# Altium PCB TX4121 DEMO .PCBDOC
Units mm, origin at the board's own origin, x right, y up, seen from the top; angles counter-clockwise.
Board outline 43.09 x 22 mm, 3 copper layers (TopLayer, MidLayer5, BottomLayer); 14 components, 16 nets, 40 pads, 90 vias.
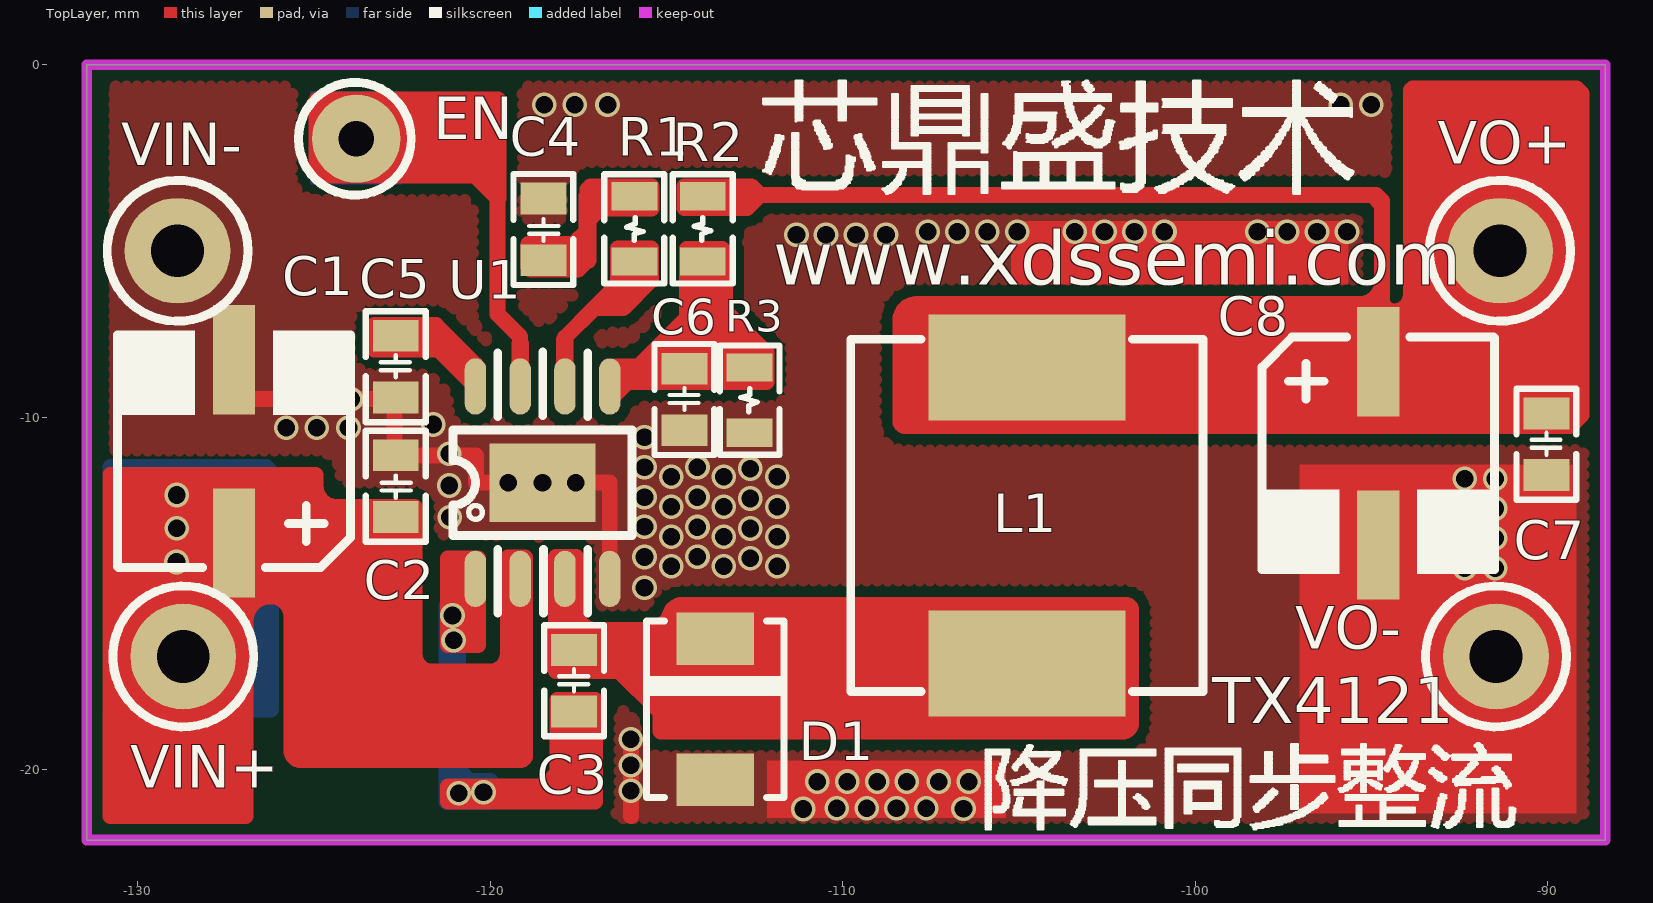
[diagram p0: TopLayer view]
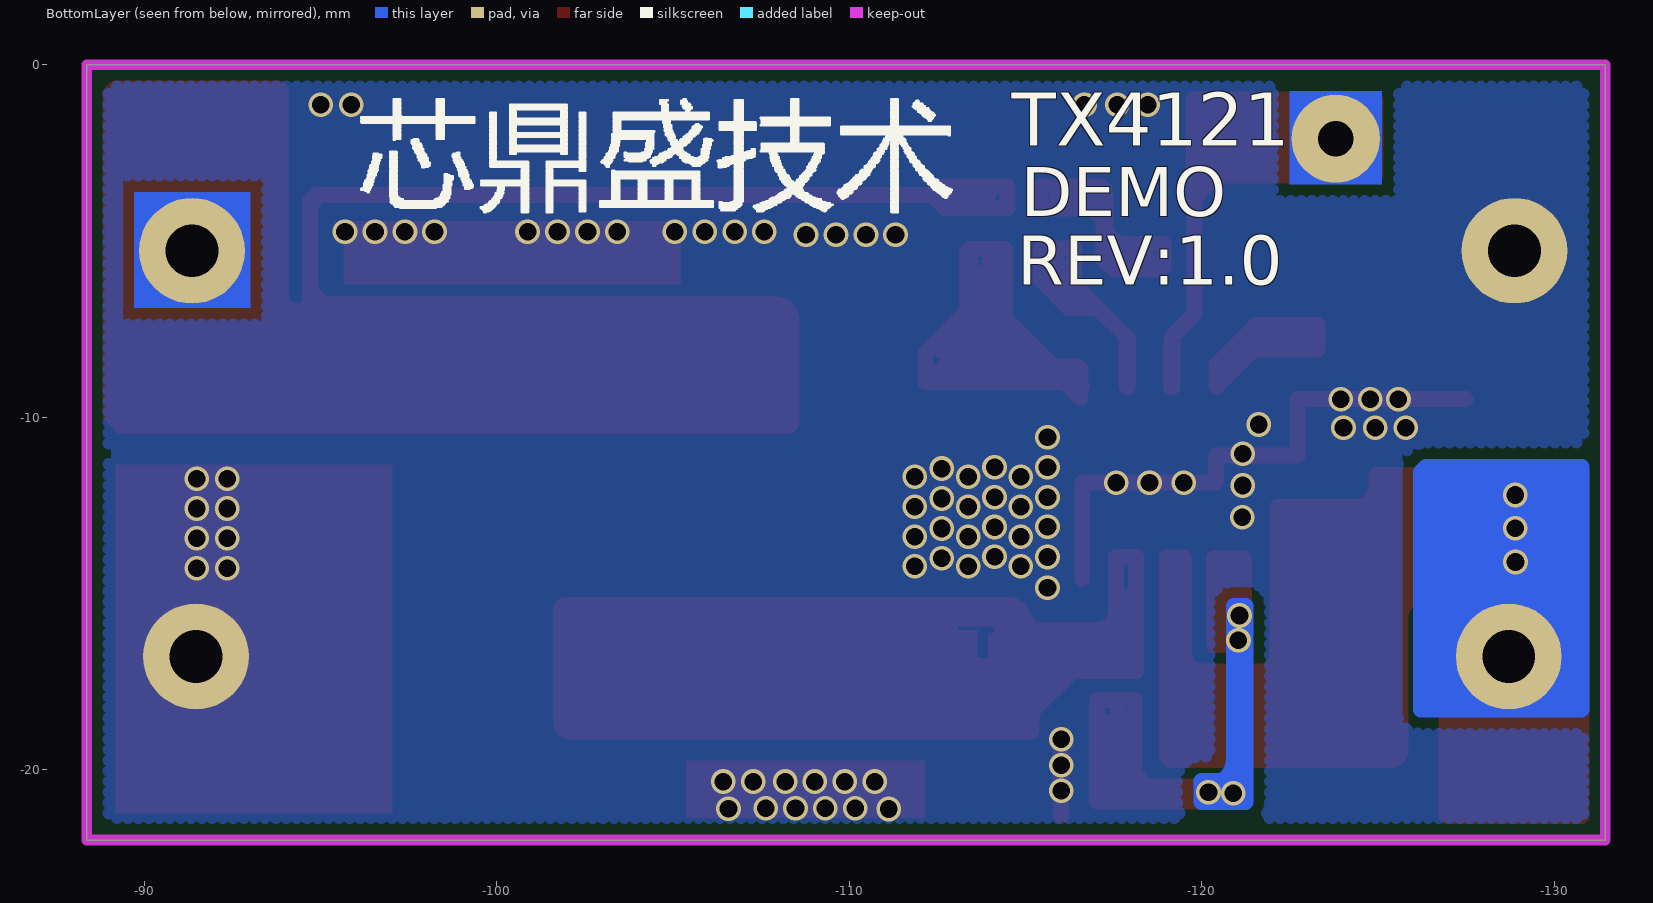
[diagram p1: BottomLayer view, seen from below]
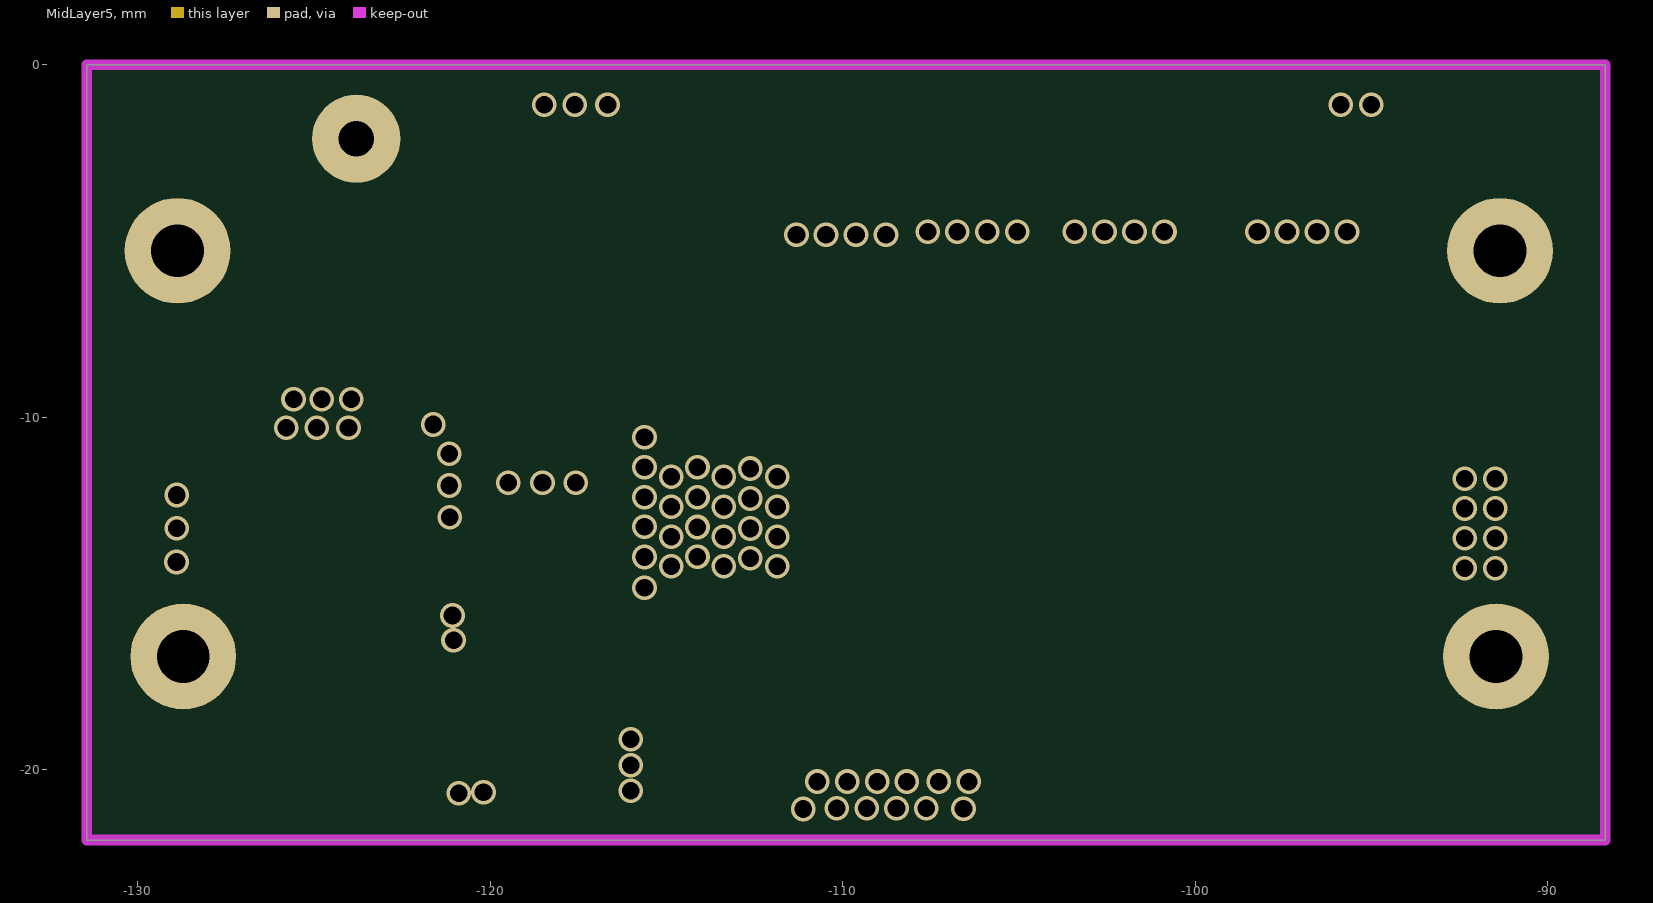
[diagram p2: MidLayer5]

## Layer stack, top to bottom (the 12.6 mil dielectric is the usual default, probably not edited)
TopLayer: signal copper 0.0356
Dielectric: dielectric 0.32, FR-4, Dk 4.8
MidLayer5: signal copper 0.0356
Dielectric: dielectric 0.32, FR-4, Dk 4.8
BottomLayer: signal copper 0.0356

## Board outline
-131.45,-22 -88.36,-22 -88.36,0 -131.45,0

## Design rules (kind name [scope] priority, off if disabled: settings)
Clearance [All] p1: gap=0.3
PlaneConnect [All] p1: planeconnectstyle=Direct reliefexpansion=0.508 reliefentries=4 reliefconductorwidth=0.254 reliefairgap=0.254
PolygonConnect [All] p1: connectstyle=Direct reliefconductorwidth=0.254 reliefentries=4 polygonreliefangle="90 Angle"
RoutingLayers [All] p1: top layer_v5=TRUE mid layer 5_v5=FALSE bottom layer_v5=TRUE
RoutingVias [All] p1: holewidth=0.711 width=1.27 viastyle="Through Hole" minholewidth=0.711 minwidth=1.27 maxholewidth=0.711 maxwidth=1.27
SilkscreenOverComponentPads [All] p1: minsilkscreentomaskgap=0.254
SolderMaskExpansion [All] p1: expansion=0.102
TestPointUsage [All] p1: valid=0 allowmultiple=FALSE
Testpoint [All] p1: side=15 testpointundercomponent=TRUE minsize=1.016 maxsize=2.54 preferedsize=1.524 minholesize=0.508 maxholesize=1.016 preferedholesize=0.813 testpointgrid=0.025 style=1023 order=0123456789
Width [All] p1: maxlimit=1 minlimit=0.3 preferedwidth=0.45
21 further rules are at their usual default settings.

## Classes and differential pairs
component class HX1304B: C1 C3 C4 C6 F1 L1 R1 R2 R3 U1

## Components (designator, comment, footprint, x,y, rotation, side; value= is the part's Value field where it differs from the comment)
C1 "100uF" C6.3*2.5W -127.27,-13.57 r180 top
C2 "100nF" C0805 -122.68,-11.96 r90 top
C3 "100nF" C0805 -117.62,-17.48 r270 top
C4 "100pF" C0805 -118.49,-4.675 r90 top
C5 "100nF" C0805 -122.68,-8.57 r270 top
C6 "47pF" C0805 -114.49,-9.5 r270 top
C7 "100nF" C0805 -90.03,-10.77 r270 top
C8 "100uF" C6.3*2.5W -94.8,-8.43 r0 top
D1 "" SMB -113.61,-18.29 r270 top
L1 "22uH" ls10*10 -104.77,-16.99 r270 top
R1 "300KΩ" R0805 -115.91,-4.66 r90 top
R2 "47kΩ" R0805 -113.97,-4.66 r270 top
R3 "10kΩ" R0805 -112.64,-9.52 r270 top
U1 "TX4121" ESOP8 -120.42,-14.59 r0 top

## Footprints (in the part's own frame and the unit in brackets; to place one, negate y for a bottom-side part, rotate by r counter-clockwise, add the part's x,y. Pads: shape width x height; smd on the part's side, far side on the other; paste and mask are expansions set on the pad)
C6.3*2.5W [mm]
  rect 1.2x3.1 smd: 1(0,0) 2(0,-5.2)
  silkscreen extent -3.3,-6.03 3.3,0.7
C0805 [mm]
  rect 0.9x1.3 smd: 1(-0.875,0) 2(0.875,0)
  silkscreen extent -1.58,-0.85 1.58,0.85
ESOP8 [mm]
  oval 0.61x1.6 smd: 1(0,0) 2(1.27,0) 3(2.54,0) 4(3.81,0) 5(3.81,5.46) 6(2.54,5.46) 7(1.27,5.46) 8(0,5.46)
  rect 3x2.23 smd: 9(1.905,2.73)
  silkscreen extent -0.64,-0.96 4.45,6.44
ls10*10 [mm]
  rect 3x5.6 smd: 1(0,0) 2(-8.4,0)
  silkscreen extent -9.2,-5 0.8,5
R0805 [mm]
  rect 0.8x1.3 smd: 1(-0.925,0) 2(0.925,0)
  silkscreen extent -1.55,-0.85 1.55,0.85
SMB [mm]
  rect 1.5x2.2 smd: 1(2,0) 2(-2,0)
  silkscreen extent -2.5,-1.97 2.5,1.95

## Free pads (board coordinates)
  round 2.5 hole 1: 0(-123.8,-2.1)
  round 3 hole 1.5: 2(-128.87,-5.28) 2(-128.71,-16.79) 2(-91.46,-16.79) 2(-91.35,-5.28)

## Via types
v1: diameter 0.7, hole 0.5, TopLayer to BottomLayer, 90 vias

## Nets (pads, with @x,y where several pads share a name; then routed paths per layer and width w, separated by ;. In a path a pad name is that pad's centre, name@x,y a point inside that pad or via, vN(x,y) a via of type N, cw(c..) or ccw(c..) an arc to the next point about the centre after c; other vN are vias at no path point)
1: 
FB: 
GND: 
ILIM: 
NetDC+_P: 
NetL1_2: 
NetR1_1: 
NetR1_2: 
NetU1_1: 
NetU1_3: 
NetU1_5: 
NetU1_8: 
RT: 
SW: 
VCC: 
VOUT: 
pads on no net: C1.1 C1.2 C2.1 C2.2 C3.1 C3.2 C4.1 C4.2 C5.1 C5.2 C6.1 C6.2 C7.1 C7.2 C8.1 C8.2 D1.1 D1.2 L1.1 L1.2 R1.1 R1.2 R2.1 R2.2 R3.1 R3.2 U1.1 U1.2 U1.3 U1.4 U1.5 U1.6 U1.7 U1.8 U1.9
copper on no net: | length 497.9
  TopLayer w0.45: -127.49,-9.49 -122.72,-9.49 -122.72,-11.085 -120.4,-11.085 -120.4,-11.86 v1(-118.515,-11.86) ; -126.94,-15.87 -126.94,-14.99 cw(c-126.5,-14.99) -126.5,-14.55 -126.47,-14.55 ; -126.94,-15.84 -126.94,-15.79 cw(c-126.23,-15.79) -126.23,-15.08 cw(c-126.23,-15.67) -125.64,-15.67 -125.64,-16.45 ; -126.94,-14.55 -124.35,-14.55 ; -126.94,-14.25 -126.91,-14.25 cw(c-126.91,-15.52) -125.64,-15.52 -125.64,-19.46 ccw(c-125.37,-19.46) -125.37,-19.73 -119.146,-19.73 ccw(c-119.146,-19.594) -119.01,-19.594 -119.01,-18.82 ; -126.94,-13.8 -126.94,-21.325 -130.775,-21.325 -130.775,-11.64 -124.95,-11.64 -124.95,-12.55 -122.68,-12.55 -122.68,-12.835 -122.68,-18.48 -119.15,-18.48 ; -126.02,-14.55 cw(c-126.02,-14.99) -125.58,-14.99 -125.58,-18.71 ccw(c-125.47,-18.71) -125.47,-18.82 -124.09,-18.82 ; -124.95,-11.95 ccw(c-124.35,-11.95) -124.35,-12.55 -123.82,-12.55 ; -124.35,-15.2 -124.35,-14.55 ; -124.35,-13.8 -124.35,-18.48 -119.15,-18.48 ; -123.68,-12.55 -122.14,-12.55 -122.14,-18.48 -121.37,-18.48 ; -123.29,-7.7 -121.85,-7.7 -120.42,-9.13 ; -122.14,-17.22 -119.5,-17.22 -119.5,-13.98 -119.01,-13.98 -119.01,-18.48 -119.48,-18.48 ; -122.14,-16.73 ccw(c-121.65,-16.73) -121.65,-17.22 -121.49,-17.22 ; v1@-121.2,-20.59 -117.03,-20.59 -117.03,-18.03 -117.62,-18.03 ; -120.98,-3.12 -120.46,-3.12 -119.79,-3.79 ; -120.59,-17.22 -120.01,-17.22 ccw(c-120.01,-16.71) -119.5,-16.71 ; -120.46,-9.09 ccw(c-120.42,-9.09) -120.42,-9.13 ; -120.42,-14.59 -120.42,-14.01 -121.2,-14.01 ; -119.79,-3.51 -119.79,-7.08 -119.15,-7.72 -119.15,-7.92 ; v1@-119.25,-11.86 -116.61,-11.86 -116.61,-14.59 ; -119.15,-14 -119.15,-14.59 -119.15,-18.48 ; -119.04,-20.48 -118.47,-20.48 -118.1,-20.11 ; -119.01,-17.61 -119.01,-18.82 ; -118.13,-15.33 -118.13,-17.2 -109.43,-17.2 ; -118.1,-19.8 -118.1,-18.03 -117.62,-18.03 ; -118.1,-19.23 -118.1,-20.48 -121.2,-20.48 -121.2,-20.91 -117.03,-20.91 -117.03,-19.96 ; -117.88,-7.735 -117.88,-7.81 -117.88,-7.74 -117.05,-6.91 ; -117.62,-18.355 -117.62,-18.03 ; -117.57,-15.47 ccw(c-117,-15.47) -117,-16.04 -116.77,-16.04 ; -117.24,-5.55 -117.51,-5.82 -118.84,-5.82 -118.92,-5.74 -118.92,-5.08 -117.63,-5.08 -117.24,-4.69 ; -117.24,-4.76 -117.24,-3.54 -117.15,-3.45 -115.42,-3.45 -115.42,-4.08 -116.87,-4.08 -117.24,-4.45 ; -116.56,-9.46 -116.03,-8.93 -112.41,-8.93 -112.23,-8.75 ; -116.47,-16.04 -115.25,-16.04 -114.92,-15.71 ; -116.32,-17.22 -115.25,-18.29 ; -116.01,-21.325 v1(-116.01,-19.141) ; -115.89,-5.605 ccw(c-115.91,-5.605) -115.91,-5.585 -115.91,-6.25 -116.57,-6.91 ; -114.33,-16.04 -117.57,-16.04 -117.57,-13.97 -118.13,-13.97 -118.13,-15.85 -118.13,-17.06 -110.414,-17.06 ; -113.97,-8.85 -113.97,-5.585 ; -113.93,-3.695 -110.09,-3.695 ; -113.33,-9 -113.33,-5.32 -113.42,-5.23 ; -112.78,-8.605 -116.085,-8.605 -116.61,-9.13 -116.48,-9 -112.16,-9 -112.16,-8.17 -113.42,-6.91 -113.42,-5.23 ; -112.64,-8.595 -112.675,-8.56 -116.31,-8.56 ; -112.35,-3.695 -112.595,-3.45 -114.49,-3.45 -114.49,-4.07 -112.715,-4.07 -112.34,-3.695 ; -111.12,-3.695 -96.585,-3.695 ; -109.8,-18.92 -102.05,-18.92 ccw(c-102.05,-18.69) -101.82,-18.69 -101.82,-15.47 ccw(c-101.96,-15.47) -101.96,-15.33 -114.54,-15.33 ccw(c-114.54,-15.71) -114.92,-15.71 ; -108.97,-18.92 -115.155,-18.92 cw(c-115.155,-18.909) -115.167,-18.909 -115.167,-18.373 ccw(c-115.25,-18.373) -115.25,-18.29 ; -108.71,-15.71 -114.92,-15.71 ; -108.48,-18.92 -110.25,-18.92 -110.88,-18.29 -115.25,-18.29 ; -97.56,-3.695 -95.055,-3.695 ; -96.93,-10.25 -89.34,-10.25 -89.035,-9.945 -89.035,-0.815 -89.175,-0.675 -92.985,-0.675 ; -95.72,-3.695 -94.975,-3.695 -94.7,-3.97 -94.7,-4.81 ; -95.66,-10.25 -108.23,-10.25 cw(c-108.23,-10.12) -108.36,-10.12 -108.36,-7.25 ; -95.41,-3.695 -94.865,-3.695 -94.7,-3.86 -94.7,-5.03 ; -95.39,-7.68 -99.83,-7.68 -94.1,-7.68 -93.88,-7.46 -93.88,-0.73 -93.825,-0.675 -92.985,-0.675 ; -94.7,-7.43 -94.7,-5.58 ; -94.7,-6.99 -94.7,-7.46 -94.48,-7.68 ; -94.7,-6.58 cw(c-95.22,-6.58) -95.22,-7.1 -108.21,-7.1 ccw(c-108.21,-7.25) -108.36,-7.25 ; -94.7,-6.17 cw(c-95.32,-6.17) -95.32,-6.79 -107.9,-6.79 ccw(c-107.9,-7.25) -108.36,-7.25 ; -94.7,-4.05 -94.7,-5.58 ; -93.88,-6.44 -93.88,-6.53 cw(c-94.35,-6.53) -94.35,-7 cw(c-94.35,-6.65) -94.7,-6.65 -94.7,-5.58 ; -93.1,-0.79 -92.985,-0.675 ; -124.35,-14.55 -124.35,-18.82 -119.01,-18.82 ; -121.2,-14.01 -121.2,-16.47 -120.34,-16.47 -120.34,-14.01 -121.2,-14.01 ; -120.42,-9.13 -121.46,-8.09 -123.29,-8.09 -123.29,-7.39 -121.54,-7.39 -120.42,-8.51 -120.42,-9.13 ; -117.05,-6.91 -116.26,-6.12 -115.44,-6.12 ; -117.05,-6.91 -116.37,-6.23 -116.37,-5.21 -115.44,-5.21 -115.44,-6.12 ; -117.05,-6.91 -116.57,-6.91 ; -116.57,-6.91 -116.23,-6.91 -115.44,-6.12 ; -116.31,-8.56 -115.79,-8.56 -114.42,-7.19 -114.42,-5.23 -113.42,-5.23 ; -116.31,-8.56 -116.47,-8.56 -116.56,-8.65 -116.56,-8.81 -116.31,-8.56
  TopLayer w0.5: -119.79,-3.79 -119.79,-3.12 -124.91,-3.12 -124.91,-1.01 -119.79,-1.01 -119.79,-3.51 ; -119.15,-9.13 -119.15,-7.92 ; -118.49,-5.55 -117.24,-5.55 -117.24,-3.735 -115.91,-3.735 ; -117.88,-9.13 -117.88,-7.81
  MidLayer5 w0.064: -74.788,-46.4 ccw(c-74.82,-46.4) -74.788,-46.4 ; -74.788,-46.4 ccw(c-74.82,-46.4) -74.788,-46.4 ; -17.478,-25.1 ccw(c-17.51,-25.1) -17.478,-25.1 ; -17.478,-25.1 ccw(c-17.51,-25.1) -17.478,-25.1 ; -74.788,5.103 ccw(c-74.82,5.103) -74.788,5.103 ; -61.588,-46.4 ccw(c-61.62,-46.4) -61.588,-46.4 ; -51.077,-29.209 ccw(c-51.109,-29.209) -51.077,-29.209 ; -51.077,-20.747 ccw(c-51.109,-20.747) -51.077,-20.747 ; -43.499,-20.782 ccw(c-43.531,-20.782) -43.499,-20.782 ; -35.988,5.103 ccw(c-36.02,5.103) -35.988,5.103 ; -17.478,26.403 ccw(c-17.51,26.403) -17.478,26.403 ; -12.277,-20.747 ccw(c-12.309,-20.747) -12.277,-20.747 ; -4.699,-20.782 ccw(c-4.731,-20.782) -4.699,-20.782 ; -4.278,-25.1 ccw(c-4.31,-25.1) -4.278,-25.1
  BottomLayer w0.45: -128.48,-11.42 -126.36,-11.42 -126.225,-11.555 -126.225,-18.295 -130.775,-18.295 -130.775,-11.42 -127.76,-11.42 -127.33,-11.85 ; -121.24,-20.32 -119.99,-20.32 -119.99,-20.92 -121.24,-20.92 -121.24,-15.36 -120.91,-15.36 -120.91,-20.43 v1@-120.19,-20.43 ; -120.91,-19.53 -120.91,-19.71 ccw(c-120.19,-19.71) v1@-120.19,-20.43 ; v1(-120.19,-20.64) v1@-120.19,-20.43
  other v1: -111.121,-21.12 -106.571,-21.11 -110.171,-21.1 -109.321,-21.1 -108.471,-21.1 -107.631,-21.1 -120.89,-20.67 -116.01,-20.6 -110.72,-20.341 -109.87,-20.341 -109.02,-20.341 -108.18,-20.341 -107.27,-20.341 -106.42,-20.341 -116.01,-19.88 -121.04,-16.33 -121.07,-15.63 -115.621,-14.84 -92.35,-14.291 -91.48,-14.291 -114.86,-14.231 -113.37,-14.231 -111.86,-14.231 -128.9,-14.11 -112.621,-14 -115.621,-13.97 -114.121,-13.96 -92.35,-13.441 -91.48,-13.441 -114.86,-13.391 -113.37,-13.391 -111.86,-13.391 -112.621,-13.16 -128.89,-13.15 -115.621,-13.11 -114.121,-13.12 -121.15,-12.841 -92.35,-12.591 -91.48,-12.591 -114.86,-12.541 -113.37,-12.541 -111.86,-12.541 -112.621,-12.31 -115.621,-12.27 -114.121,-12.27 -128.89,-12.21 -121.16,-11.941 -119.49,-11.86 -117.57,-11.86 -92.35,-11.751 -91.48,-11.751 -114.86,-11.691 -113.37,-11.691 -111.86,-11.691 -112.621,-11.46 -115.621,-11.42 -114.121,-11.42 -121.16,-11.041 -115.621,-10.57 -125.79,-10.3 -124.921,-10.3 -124.021,-10.3 -121.621,-10.21 -125.58,-9.49 -124.78,-9.49 -123.94,-9.49 -111.311,-4.83 -110.471,-4.83 -109.621,-4.83 -108.771,-4.83 -107.59,-4.741 -106.75,-4.741 -105.9,-4.741 -105.05,-4.741 -103.41,-4.741 -102.57,-4.741 -101.72,-4.741 -100.87,-4.741 -98.23,-4.741 -97.39,-4.741 -96.54,-4.741 -95.69,-4.741 -118.47,-1.141 -117.6,-1.141 -116.67,-1.141 -95.87,-1.141 -95,-1.141

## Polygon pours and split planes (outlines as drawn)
no net on TopLayer "TopLayer-No Net" (hatched 90Degree grid 0.3 track 0.35, pour order 1007): -116.55,-21.53 -88.69,-21.53 -88.69,-10.23 -93.69,-10.23 -93.69,-0.54 -130.65,-0.54 -130.65,-11.35 -124.73,-11.35 -124.73,-12.53 -121.92,-12.53 -121.92,-13.71 -116.97,-13.71 -116.97,-21.54 -116.44,-21.54
no net on BottomLayer "BottomLayer-No Net" (hatched 90Degree grid 0.3 track 0.35, pour order 1017): -88.93,-21.47 -130.92,-21.47 -130.92,-0.49 -88.96,-0.49 -88.96,-21.44
GND on MultiLayer (hatched 90Degree grid 0.08 track 0.1, remove dead copper): -82.62,-489.9

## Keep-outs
KeepOutLayer:
  lines w0.3: -131.45,-22 -88.36,-22 ; -131.45,-22 -131.45,-11 -131.45,0 -88.36,0 ; -131.45,-22 -88.36,-22 ; -88.36,-22 -88.36,-11 -88.36,0 ; -88.36,-22 -88.36,0

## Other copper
TopLayer:
  rectangle: -95.22,-8.2 -92.88,-7.1
  rectangle: -108.21,-10.25 -94.69,-7.1
  rectangle: -127.37,-15.31 -125.58,-14.43
  region: -95.65,-4.441 -105.23,-4.441 -105.23,-6.241 -95.65,-6.241
  region: -105.36,-19.741 -112.15,-19.741 -112.15,-21.375 -105.36,-21.375
  region: -97.095,-10.415 -97.095,-9.54 -98.36,-9.54 -98.36,-10.415
  rectangle: -99.83,-10.25 -93.11,-7.68
  rectangle: -93.88,-10.139 -89.229,-0.73
  rectangle: -114.81,-7.87 -113.97,-7.45
  rectangle: -114.42,-7.84 -113.18,-5.69
  rectangle: -113.48,-7.94 -112.9,-7.38
  rectangle: -112.9,-8.33 -112.45,-7.94
  rectangle: -115.25,-8.625 -114.49,-8.01
  rectangle: -114.92,-8.595 -112.64,-7.69
  rectangle: -118.09,-5.55 -117.24,-5.08
  rectangle: -115.82,-17.87 -115.25,-17.2
  rectangle: -115.46,-18.29 -113.04,-17.06
  rectangle: -110.8,-18.51 -110.22,-17.99
  rectangle: -113.63,-18.22 -110.17,-16.04
  rectangle: -124.91,-3.01 -119.79,-1.01
  rectangle: -118.13,-17.2 -113.94,-16.13
  rectangle: -118.13,-16.605 -117.62,-14.87
  rectangle: -121.2,-16.47 -120.34,-14.01
  rectangle: -118.1,-20.33 -117.03,-18.44
  rectangle: -118.1,-20.91 -117.03,-19.82
  rectangle: -124.35,-18.82 -119.01,-17.2
  rectangle: -124.37,-17.53 -122.14,-12.55
  rectangle: -130.775,-14.63 -124,-12.58
  rectangle: -130.775,-13.45 -125.09,-11.64
  rectangle: -130.775,-21.325 -126.94,-13.17
  rectangle: -125.49,-18.82 -124.05,-14.55
  rectangle: -125.58,-19.594 -119.01,-18.27
  region: -89.18,-11.341 -97.031,-11.341 -97.031,-21.241 -89.18,-21.241
  rectangle: -110.12,-18.98 -101.77,-15.33
  rectangle: -110.5,-18.92 -109.67,-18.13
  rectangle: -113.09,-18.44 -109.31,-15.71
  rectangle: -114.98,-18.92 -110.52,-17.87
BottomLayer:
  region: -122.49,-0.74 -125.12,-0.74 -125.12,-3.4 -122.49,-3.4
  region: -126.225,-11.42 -130.775,-11.42 -130.775,-18.295 -126.225,-18.295
  region: -89.7,-6.9 -89.7,-3.61 -93.01,-3.61 -93.01,-6.9
  rectangle: -121.24,-20.92 -119.99,-20.35

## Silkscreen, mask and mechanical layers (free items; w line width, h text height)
TopOverlay:
  drawing of 2416 lines, arcs and shapes, not listed
  text "EN" at -121.62,-2.12 h1.2
  text "VO+" at -93.11,-2.81 h1.2
  text "VIN-" at -130.47,-2.85 h1.2
  text "www.xdssemi.com" at -111.97,-6.241 h1.52
  text "VO-" at -97.16,-16.57 h1.2
  text "TX4121" at -99.52,-18.68 h1.3
  text "VIN+" at -130.22,-20.52 h1.2
BottomOverlay:
  drawing of 1289 lines, arcs and shapes, not listed
  text "TX4121" at -114.601,-2.3 h1.5
  text "DEMO" at -114.861,-4.3 h1.4
  text "REV:1.0" at -114.761,-6.25 h1.4
TopSolder:
  rectangle: -95.54,-16.839 -93.34,-14.25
